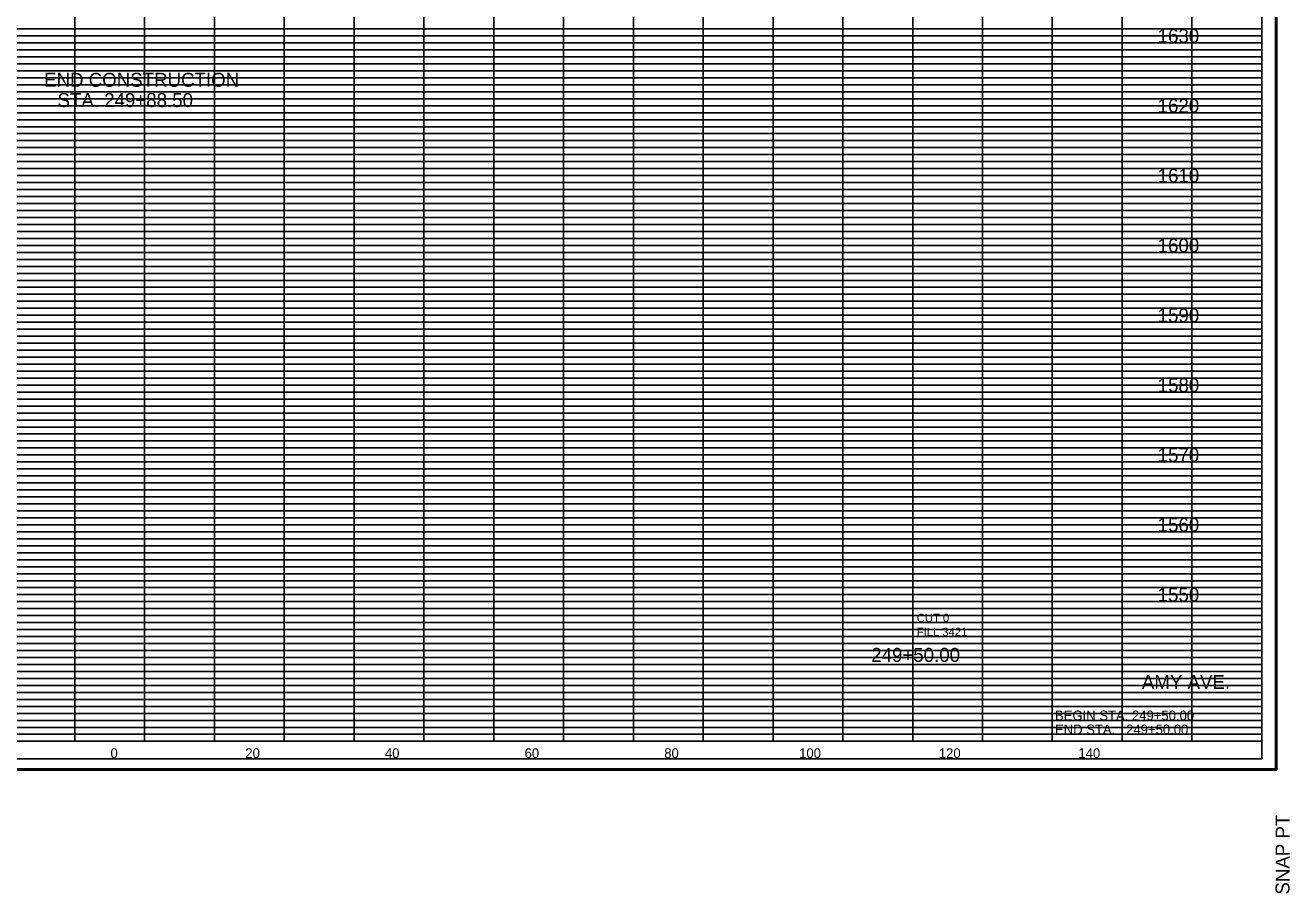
# Model space of a CAD drawing. Extents: x 955 to 1375, y 1248 to 3657.
# Drawn here: x 1142.9 to 1324, y 3408.2 to 3532.5 of the extents above; entities that cross this region are included whole.
import ezdxf

# ---------------------------------------------------------------- set-up
doc = ezdxf.new("R2010")
doc.units = 0
for name, color, linetype in [('DESIGN - SHEET - Corner Text', 7, 'Continuous'), ('DESIGN - SHEET - Light Grid', 7, 'Continuous'), ('DESIGN - SHEET - Linework', 7, 'Continuous'), ('DESIGN - SHEET - Plot Shape', 7, 'Continuous'), ('DESIGN - TYPICAL - Text', 7, 'Continuous'), ('DESIGN - UTILITIES - Cable (Overhead) with Text', 7, 'Continuous')]:
    doc.layers.add(name, color=color, linetype=linetype)

# ---------------------------------------------------------------- blocks, each defined once
blk = doc.blocks.new('XSTSHT')
at = {"layer": 'DESIGN - SHEET - Light Grid'}
for p, q in [((8, 10.2), (16, 10.2)), ((16, 10.2), (24, 10.2)), ((24, 10.2), (32, 10.2)), ((8, 10.1), (16, 10.1)), ((16, 10.1), (24, 10.1)), ((24, 10.1), (32, 10.1)), ((8, 9.9), (16, 9.9)), ((8, 9.8), (16, 9.8)), ((16, 9.9), (24, 9.9)), ((16, 9.8), (24, 9.8)), ((24, 9.9), (32, 9.9)), ((24, 9.8), (32, 9.8)), ((8, 9.7), (16, 9.7)), ((8, 9.6), (16, 9.6)), ((16, 9.7), (24, 9.7)), ((16, 9.6), (24, 9.6)), ((24, 9.7), (32, 9.7)), ((24, 9.6), (32, 9.6)), ((8, 9.5), (16, 9.5)), ((16, 9.5), (24, 9.5)), ((24, 9.5), (32, 9.5)), ((8, 9.4), (16, 9.4)), ((8, 9.3), (16, 9.3)), ((16, 9.4), (24, 9.4)), ((16, 9.3), (24, 9.3)), ((24, 9.4), (32, 9.4)), ((24, 9.3), (32, 9.3)), ((8, 9.2), (16, 9.2)), ((8, 9.1), (16, 9.1)), ((16, 9.2), (24, 9.2)), ((16, 9.1), (24, 9.1)), ((24, 9.2), (32, 9.2)), ((24, 9.1), (32, 9.1)), ((8, 8.9), (16, 8.9)), ((16, 8.9), (24, 8.9)), ((24, 8.9), (32, 8.9)), ((8, 8.8), (16, 8.8)), ((8, 8.7), (16, 8.7)), ((16, 8.8), (24, 8.8)), ((16, 8.7), (24, 8.7)), ((24, 8.8), (32, 8.8)), ((24, 8.7), (32, 8.7)), ((8, 8.6), (16, 8.6)), ((16, 8.6), (24, 8.6)), ((24, 8.6), (32, 8.6)), ((8, 8.5), (16, 8.5)), ((8, 8.4), (16, 8.4)), ((16, 8.5), (24, 8.5)), ((16, 8.4), (24, 8.4)), ((24, 8.5), (32, 8.5)), ((24, 8.4), (32, 8.4)), ((8, 8.3), (16, 8.3)), ((8, 8.2), (16, 8.2)), ((16, 8.3), (24, 8.3)), ((16, 8.2), (24, 8.2)), ((24, 8.3), (32, 8.3)), ((24, 8.2), (32, 8.2)), ((8, 8.1), (16, 8.1)), ((16, 8.1), (24, 8.1)), ((24, 8.1), (32, 8.1)), ((8, 7.9), (16, 7.9)), ((8, 7.8), (16, 7.8)), ((16, 7.9), (24, 7.9)), ((16, 7.8), (24, 7.8)), ((24, 7.9), (32, 7.9)), ((24, 7.8), (32, 7.8)), ((8, 7.7), (16, 7.7)), ((16, 7.7), (24, 7.7)), ((24, 7.7), (32, 7.7)), ((8, 7.6), (16, 7.6)), ((8, 7.5), (16, 7.5)), ((16, 7.6), (24, 7.6)), ((16, 7.5), (24, 7.5)), ((24, 7.6), (32, 7.6)), ((24, 7.5), (32, 7.5)), ((8, 7.4), (16, 7.4)), ((8, 7.3), (16, 7.3)), ((16, 7.4), (24, 7.4)), ((16, 7.3), (24, 7.3)), ((24, 7.4), (32, 7.4)), ((24, 7.3), (32, 7.3)), ((8, 7.2), (16, 7.2)), ((8, 7.1), (16, 7.1)), ((16, 7.2), (24, 7.2)), ((16, 7.1), (24, 7.1)), ((24, 7.2), (32, 7.2)), ((24, 7.1), (32, 7.1)), ((8, 6.9), (16, 6.9)), ((16, 6.9), (24, 6.9)), ((24, 6.9), (32, 6.9)), ((8, 6.8), (16, 6.8)), ((16, 6.8), (24, 6.8)), ((24, 6.8), (32, 6.8)), ((8, 6.7), (16, 6.7)), ((8, 6.6), (16, 6.6)), ((16, 6.7), (24, 6.7)), ((16, 6.6), (24, 6.6)), ((24, 6.7), (32, 6.7)), ((24, 6.6), (32, 6.6)), ((8, 6.5), (16, 6.5)), ((8, 6.4), (16, 6.4)), ((16, 6.5), (24, 6.5)), ((16, 6.4), (24, 6.4)), ((24, 6.5), (32, 6.5)), ((24, 6.4), (32, 6.4)), ((8, 6.3), (16, 6.3)), ((8, 6.2), (16, 6.2)), ((16, 6.3), (24, 6.3)), ((16, 6.2), (24, 6.2)), ((24, 6.3), (32, 6.3)), ((24, 6.2), (32, 6.2)), ((8, 6.1), (16, 6.1)), ((16, 6.1), (24, 6.1)), ((24, 6.1), (32, 6.1)), ((8, 5.9), (16, 5.9)), ((8, 5.8), (16, 5.8)), ((16, 5.9), (24, 5.9)), ((16, 5.8), (24, 5.8)), ((24, 5.9), (32, 5.9)), ((24, 5.8), (32, 5.8)), ((8, 5.7), (16, 5.7)), ((16, 5.7), (24, 5.7)), ((24, 5.7), (32, 5.7)), ((8, 5.6), (16, 5.6)), ((8, 5.5), (16, 5.5)), ((16, 5.6), (24, 5.6)), ((16, 5.5), (24, 5.5)), ((24, 5.6), (32, 5.6)), ((24, 5.5), (32, 5.5)), ((8, 5.4), (16, 5.4)), ((8, 5.3), (16, 5.3)), ((16, 5.4), (24, 5.4)), ((16, 5.3), (24, 5.3)), ((24, 5.4), (32, 5.4)), ((24, 5.3), (32, 5.3)), ((8, 5.2), (16, 5.2)), ((8, 5.1), (16, 5.1)), ((16, 5.2), (24, 5.2)), ((16, 5.1), (24, 5.1)), ((24, 5.2), (32, 5.2)), ((24, 5.1), (32, 5.1)), ((8, 4.9), (16, 4.9)), ((16, 4.9), (24, 4.9)), ((24, 4.9), (32, 4.9)), ((8, 4.8), (16, 4.8)), ((16, 4.8), (24, 4.8)), ((24, 4.8), (32, 4.8)), ((8, 4.7), (16, 4.7)), ((8, 4.6), (16, 4.6)), ((16, 4.7), (24, 4.7)), ((16, 4.6), (24, 4.6)), ((24, 4.7), (32, 4.7)), ((24, 4.6), (32, 4.6)), ((8, 4.5), (16, 4.5)), ((8, 4.4), (16, 4.4)), ((16, 4.5), (24, 4.5)), ((16, 4.4), (24, 4.4)), ((24, 4.5), (32, 4.5)), ((24, 4.4), (32, 4.4)), ((8, 4.3), (16, 4.3)), ((8, 4.2), (16, 4.2)), ((16, 4.3), (24, 4.3)), ((16, 4.2), (24, 4.2)), ((24, 4.3), (32, 4.3)), ((24, 4.2), (32, 4.2)), ((8, 4.1), (16, 4.1)), ((16, 4.1), (24, 4.1)), ((24, 4.1), (32, 4.1)), ((8, 3.9), (16, 3.9)), ((16, 3.9), (24, 3.9)), ((24, 3.9), (32, 3.9)), ((8, 3.8), (16, 3.8)), ((8, 3.7), (16, 3.7)), ((16, 3.8), (24, 3.8)), ((16, 3.7), (24, 3.7)), ((24, 3.8), (32, 3.8)), ((24, 3.7), (32, 3.7)), ((8, 3.6), (16, 3.6)), ((8, 3.5), (16, 3.5)), ((16, 3.6), (24, 3.6)), ((16, 3.5), (24, 3.5)), ((24, 3.6), (32, 3.6)), ((24, 3.5), (32, 3.5)), ((8, 3.4), (16, 3.4)), ((8, 3.3), (16, 3.3)), ((16, 3.4), (24, 3.4)), ((16, 3.3), (24, 3.3)), ((24, 3.4), (32, 3.4)), ((24, 3.3), (32, 3.3)), ((8, 3.2), (16, 3.2)), ((8, 3.1), (16, 3.1)), ((16, 3.2), (24, 3.2)), ((16, 3.1), (24, 3.1)), ((24, 3.2), (32, 3.2)), ((24, 3.1), (32, 3.1)), ((8, 2.9), (16, 2.9)), ((16, 2.9), (24, 2.9)), ((24, 2.9), (32, 2.9)), ((8, 2.8), (16, 2.8)), ((16, 2.8), (24, 2.8)), ((24, 2.8), (32, 2.8)), ((8, 2.7), (16, 2.7)), ((8, 2.6), (16, 2.6)), ((16, 2.7), (24, 2.7)), ((16, 2.6), (24, 2.6)), ((24, 2.7), (32, 2.7)), ((24, 2.6), (32, 2.6)), ((8, 2.5), (16, 2.5)), ((8, 2.4), (16, 2.4)), ((16, 2.5), (24, 2.5)), ((16, 2.4), (24, 2.4)), ((24, 2.5), (32, 2.5)), ((24, 2.4), (32, 2.4)), ((8, 2.3), (16, 2.3)), ((8, 2.2), (16, 2.2)), ((16, 2.3), (24, 2.3)), ((16, 2.2), (24, 2.2)), ((24, 2.3), (32, 2.3)), ((24, 2.2), (32, 2.2)), ((8, 2.1), (16, 2.1)), ((16, 2.1), (24, 2.1)), ((24, 2.1), (32, 2.1)), ((8, 1.9), (16, 1.9)), ((16, 1.9), (24, 1.9)), ((24, 1.9), (32, 1.9)), ((8, 1.8), (16, 1.8)), ((8, 1.7), (16, 1.7)), ((16, 1.8), (24, 1.8)), ((16, 1.7), (24, 1.7)), ((24, 1.8), (32, 1.8)), ((24, 1.7), (32, 1.7)), ((8, 1.6), (16, 1.6)), ((8, 1.5), (16, 1.5)), ((16, 1.6), (24, 1.6)), ((16, 1.5), (24, 1.5)), ((24, 1.6), (32, 1.6)), ((24, 1.5), (32, 1.5)), ((8, 1.4), (16, 1.4)), ((8, 1.3), (16, 1.3)), ((16, 1.4), (24, 1.4)), ((16, 1.3), (24, 1.3)), ((24, 1.4), (32, 1.4)), ((24, 1.3), (32, 1.3)), ((8, 1.2), (16, 1.2)), ((8, 1.1), (16, 1.1)), ((16, 1.2), (24, 1.2)), ((16, 1.1), (24, 1.1)), ((24, 1.2), (32, 1.2)), ((24, 1.1), (32, 1.1)), ((8, 0.9), (16, 0.9)), ((8, 0.8), (16, 0.8)), ((16, 0.9), (24, 0.9)), ((16, 0.8), (24, 0.8)), ((24, 0.9), (32, 0.9)), ((24, 0.8), (32, 0.8)), ((8, 0.7), (16, 0.7)), ((8, 0.6), (16, 0.6)), ((16, 0.7), (24, 0.7)), ((16, 0.6), (24, 0.6)), ((24, 0.7), (32, 0.7)), ((24, 0.6), (32, 0.6)), ((8, 0.5), (16, 0.5)), ((8, 0.4), (16, 0.4)), ((16, 0.5), (24, 0.5)), ((16, 0.4), (24, 0.4)), ((24, 0.5), (32, 0.5)), ((24, 0.4), (32, 0.4)), ((8, 0.3), (16, 0.3)), ((8, 0.2), (16, 0.2)), ((16, 0.3), (24, 0.3)), ((16, 0.2), (24, 0.2)), ((24, 0.3), (32, 0.3)), ((24, 0.2), (32, 0.2)), ((8, 0.1), (16, 0.1)), ((16, 0.1), (24, 0.1)), ((24, 0.1), (32, 0.1))]:
    blk.add_line(p, q, dxfattribs=at)
at = {"layer": 'DESIGN - SHEET - Linework'}
for p, q in [((32.217, 21.414), (32.217, -0.414)), ((15, 0), (15, 21)), ((16, 0), (16, 21)), ((17, 0), (17, 21)), ((18, 0), (18, 21)), ((19, 0), (19, 21)), ((20, 0), (20, 21)), ((21, 0), (21, 21)), ((22, 0), (22, 21)), ((23, 0), (23, 21)), ((24, 0), (24, 21)), ((25, 0), (25, 21)), ((26, 0), (26, 21)), ((27, 0), (27, 21)), ((28, 0), (28, 20)), ((29, 0), (29, 20)), ((30, 0), (30, 20)), ((31, 0), (31, 20)), ((0, 10), (32, 10)), ((0, 9), (32, 9)), ((0, 8), (32, 8)), ((0, 7), (32, 7)), ((0, 6), (32, 6)), ((0, 5), (32, 5)), ((0, 4), (32, 4)), ((0, 3), (32, 3)), ((0, 2), (32, 2)), ((0, 1), (32, 1)), ((-1.823, -0.414), (32.217, -0.414))]:
    blk.add_line(p, q, dxfattribs=at)
blk.add_lwpolyline([(0, 21), (0, 0), (32, 0), (32, 21), (0, 21)], dxfattribs=at)
at = {"layer": 'DESIGN - SHEET - Plot Shape'}
for points in [[(-1.803, 21.394), (32.197, 21.394), (32.197, -0.394), (-1.803, -0.394)], [(-0.85, 21), (32, 21), (32, -0.25), (-0.85, -0.25)]]:
    blk.add_lwpolyline(points, close=True, dxfattribs=at)
at = {"layer": 'DESIGN - SHEET - Corner Text'}
blk.add_text('SNAP PT  ', height=0.2, rotation=90, dxfattribs=at).set_placement((32.397, -2.194))

msp = doc.modelspace()

# ---------------------------------------------------------------- linework, layer by layer
at = {"layer": 'DESIGN - SHEET - Plot Shape'}
msp.add_lwpolyline([(991.5, 3427.5), (1320, 3427.5), (1320, 3640), (991.5, 3640)], close=True, dxfattribs=at)

# ---------------------------------------------------------------- block references
at = {"layer": 'DESIGN - UTILITIES - Cable (Overhead) with Text', "xscale": 10, "yscale": 10}
msp.add_blockref('XSTSHT', (1000, 3430), dxfattribs=at)

# ---------------------------------------------------------------- texts
at = {"layer": 'DESIGN - SHEET - Corner Text'}
for s, height, p in [('AMY AVE.', 2, (1302.83, 3437.5)), ('BEGIN STA. 249+50.00', 1.4, (1290.38, 3433)), ('END STA.   249+50.00', 1.4, (1290.38, 3431))]:
    msp.add_text(s, height=height, dxfattribs=at).set_placement(p)
at = {"layer": 'DESIGN - TYPICAL - Text'}
for s, height, p in [('     1630     ', 2, (1301.37, 3530)), ('END CONSTRUCTION', 2, (1145.6, 3523.71)), ('STA. 249+88.50', 2, (1147.52, 3520.81)), ('     1620     ', 2, (1301.37, 3520)), ('     1610     ', 2, (1301.37, 3510)), ('     1600     ', 2, (1301.37, 3500)), ('     1590     ', 2, (1301.37, 3490)), ('     1580     ', 2, (1301.37, 3480)), ('     1570     ', 2, (1301.37, 3470)), ('     1560     ', 2, (1301.37, 3460)), ('     1550     ', 2, (1301.37, 3450)), ('CUT 0', 1.2, (1270.59, 3447.07)), ('FILL 3421', 1.2, (1270.59, 3445.07)), ('     249+50.00     ', 2, (1260.35, 3441.37)), ('     0     ', 1.4, (1152.51, 3427.6)), ('     0     ', 1.4, (1152.51, 3427.6)), ('     20     ', 1.4, (1171.82, 3427.6)), ('     40     ', 1.4, (1191.82, 3427.6)), ('     60     ', 1.4, (1211.82, 3427.6)), ('     80     ', 1.4, (1231.82, 3427.6)), ('     100     ', 1.4, (1251.14, 3427.6)), ('     120     ', 1.4, (1271.14, 3427.6)), ('     140     ', 1.4, (1291.14, 3427.6))]:
    msp.add_text(s, height=height, dxfattribs=at).set_placement(p)

doc.saveas('drawing.dxf')
